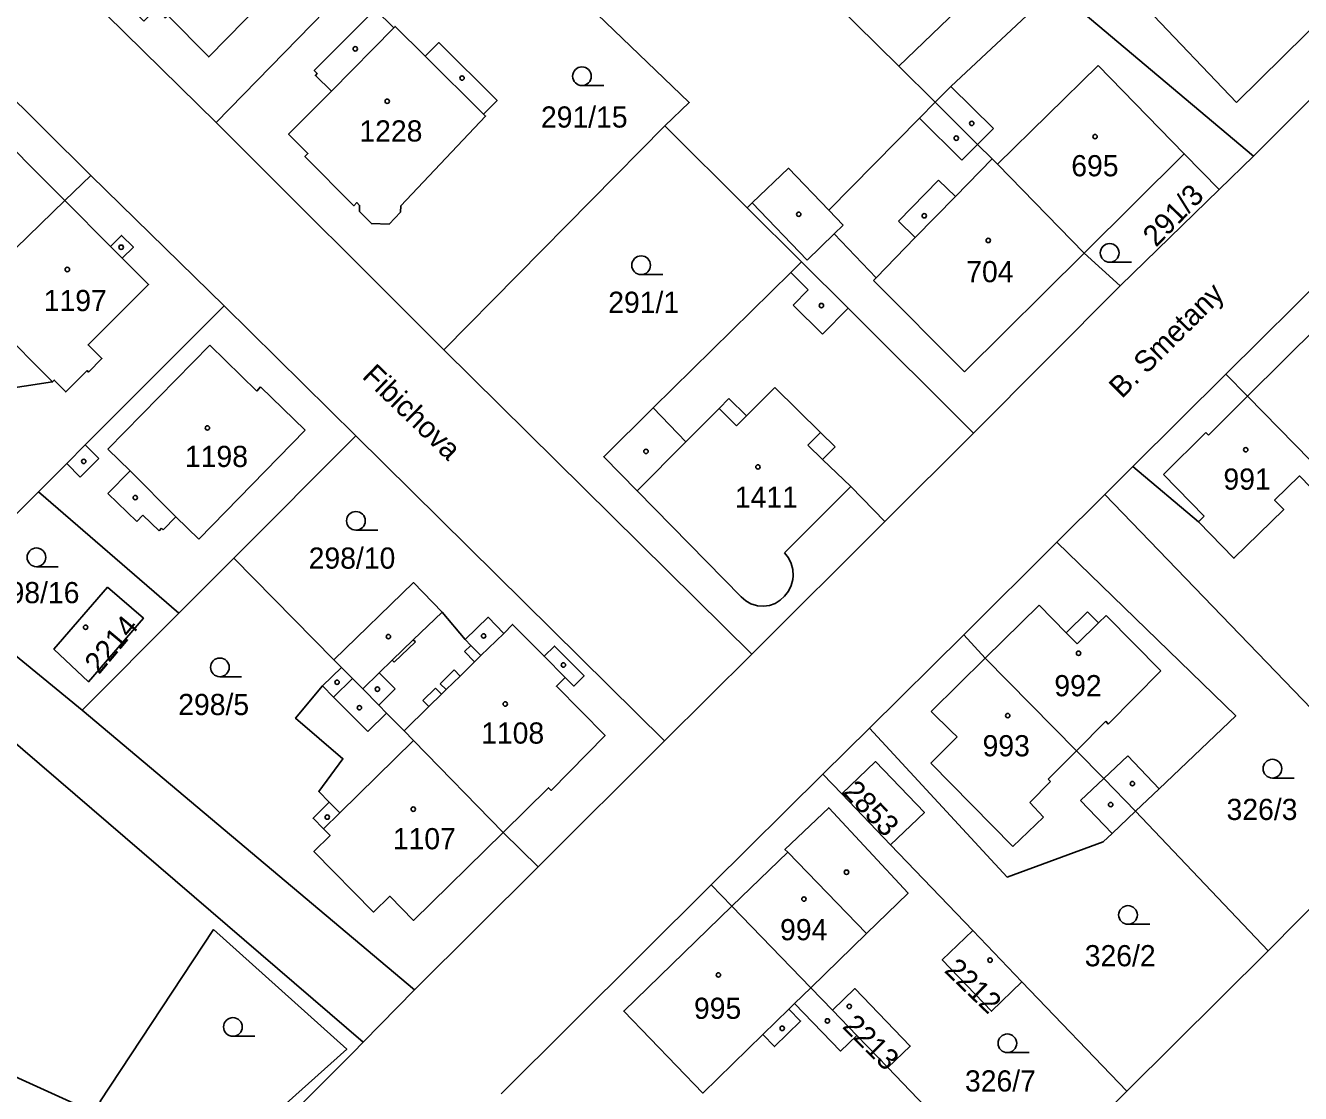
# Model space of a CAD drawing. Extents: x -679220 to -673243, y -1075091 to -1066557.
# Drawn here: x -676221 to -676118.6, y -1072295.1 to -1072209.4 of the extents above; entities that cross this region are included whole.
import ezdxf

# ---------------------------------------------------------------- set-up
doc = ezdxf.new("R2010")
doc.units = 0
for name, color, linetype in [('Hranice parcel', 7, 'Continuous'), ('Parcelní čísla', 7, 'Continuous'), ('Pop  PČ popisy', 7, 'Continuous'), ('Vnitřní kresba', 7, 'Continuous'), ('Značky budov', 7, 'Continuous'), ('Značky kultur', 7, 'Continuous')]:
    doc.layers.add(name, color=color, linetype=linetype)

msp = doc.modelspace()

# ---------------------------------------------------------------- linework, layer by layer
at = {"layer": 'Hranice parcel'}
for p, q in [((-676205.67, -1072217.2), (-676219.22, -1072203.87)), ((-676205.67, -1072217.2), (-676193.21, -1072204.43)), ((-676122.41, -1072219.9), (-676138.34, -1072206.48)), ((-676226.45, -1072210.85), (-676215.72, -1072221.46)), ((-676112.93, -1072210.41), (-676122.41, -1072219.9)), ((-676150.87, -1072212.69), (-676147.97, -1072215.57)), ((-676187.4, -1072235.45), (-676205.67, -1072217.2)), ((-676169.65, -1072217.48), (-676187.4, -1072235.45)), ((-676169.65, -1072217.48), (-676163.05, -1072224.05)), ((-676125.16, -1072222.58), (-676122.41, -1072219.9)), ((-676217.82, -1072223.47), (-676215.72, -1072221.46)), ((-676215.72, -1072221.46), (-676205.02, -1072231.91)), ((-676125.16, -1072222.58), (-676133.11, -1072230.32)), ((-676163.05, -1072224.05), (-676158.7, -1072228.38)), ((-676133.11, -1072230.32), (-676136.01, -1072227.69)), ((-676124.63, -1072237.4), (-676114.69, -1072227.54)), ((-676133.11, -1072230.32), (-676144.89, -1072242.13)), ((-676205.02, -1072231.91), (-676194.46, -1072242.34)), ((-676162.67, -1072259.88), (-676187.4, -1072235.45)), ((-676132.09, -1072244.81), (-676124.63, -1072237.4)), ((-676204.26, -1072252.16), (-676194.46, -1072242.34)), ((-676194.46, -1072242.34), (-676169.68, -1072266.83)), ((-676144.89, -1072242.13), (-676152.01, -1072249.22)), ((-676134.35, -1072247.07), (-676132.09, -1072244.81)), ((-676227.97, -1072254.9), (-676219.92, -1072246.83)), ((-676219.92, -1072246.83), (-676208.66, -1072256.58)), ((-676138.21, -1072250.89), (-676134.35, -1072247.07)), ((-676110, -1072272.34), (-676134.35, -1072247.07)), ((-676152.01, -1072249.22), (-676162.67, -1072259.88)), ((-676145.66, -1072258.33), (-676138.21, -1072250.89)), ((-676208.66, -1072256.58), (-676204.26, -1072252.16)), ((-676196.21, -1072260.33), (-676204.26, -1072252.16)), ((-676216.43, -1072264.37), (-676227.97, -1072254.9)), ((-676208.66, -1072256.58), (-676216.43, -1072264.37)), ((-676153.23, -1072265.81), (-676145.66, -1072258.33)), ((-676169.68, -1072266.83), (-676162.67, -1072259.88)), ((-676196.21, -1072260.33), (-676195.61, -1072260.93)), ((-676189.76, -1072286.8), (-676216.43, -1072264.37)), ((-676156.97, -1072269.5), (-676153.23, -1072265.81)), ((-676169.68, -1072266.83), (-676179.83, -1072276.94)), ((-676156.97, -1072269.5), (-676165.95, -1072278.37)), ((-676155.45, -1072271.09), (-676156.97, -1072269.5)), ((-676151.54, -1072275.17), (-676155.45, -1072271.09)), ((-676121.25, -1072283.67), (-676131.89, -1072272.47)), ((-676110, -1072272.34), (-676121.25, -1072283.67)), ((-676179.83, -1072276.94), (-676182.64, -1072274.17)), ((-676144.94, -1072282.06), (-676151.54, -1072275.17)), ((-676179.83, -1072276.94), (-676189.76, -1072286.8)), ((-676182.79, -1072295.17), (-676165.95, -1072278.37)), ((-676165.95, -1072278.37), (-676164.27, -1072280.1)), ((-676164.27, -1072280.1), (-676157.95, -1072286.65)), ((-676141, -1072286.18), (-676144.94, -1072282.06)), ((-676121.25, -1072283.67), (-676132.59, -1072294.95)), ((-676189.76, -1072286.8), (-676193.86, -1072291)), ((-676157.95, -1072286.65), (-676156.21, -1072288.45)), ((-676132.59, -1072294.95), (-676141, -1072286.18)), ((-676154.26, -1072290.47), (-676156.21, -1072288.45)), ((-676154.26, -1072290.47), (-676151.77, -1072293.05)), ((-676151.77, -1072293.05), (-676141.46, -1072303.74)), ((-676132.59, -1072294.95), (-676141.46, -1072303.74))]:
    msp.add_line(p, q, dxfattribs=at)
for points in [[(-676211.47, -1072209.07), (-676214.42, -1072206.17), (-676213.47, -1072205.21), (-676214.18, -1072204.52), (-676212.05, -1072202.31), (-676213.25, -1072201.15), (-676209.05, -1072196.86), (-676207.81, -1072198.07), (-676206.77, -1072197), (-676199.04, -1072204.56), (-676206.26, -1072211.94), (-676209.56, -1072208.59), (-676209.77, -1072208.81), (-676210.5, -1072208.09), (-676211.47, -1072209.07)], [(-676186.48, -1072197.53), (-676167.7, -1072215.6), (-676169.65, -1072217.48)], [(-676152.53, -1072200.63), (-676157.8, -1072205.82), (-676150.87, -1072212.69)], [(-676152.53, -1072200.63), (-676145.55, -1072207.57), (-676150.87, -1072212.69)], [(-676191.42, -1072209.6), (-676192.91, -1072208.12), (-676197.8, -1072213.04), (-676197.56, -1072213.28), (-676197.7, -1072213.43), (-676196.42, -1072214.7), (-676199.85, -1072218.15), (-676198.3, -1072219.68), (-676198.54, -1072219.92), (-676194.63, -1072223.88), (-676194.38, -1072223.63), (-676194.15, -1072223.86), (-676194.16, -1072224.35), (-676193.21, -1072225.31), (-676191.78, -1072225.35), (-676190.88, -1072224.39), (-676190.84, -1072223.89), (-676184.05, -1072216.69), (-676184.2, -1072216.54), (-676183.12, -1072215.44), (-676187.8, -1072210.79), (-676188.89, -1072211.89), (-676191.31, -1072209.49), (-676191.42, -1072209.6)], [(-676163.05, -1072224.05), (-676162.64, -1072223.66), (-676159.73, -1072220.87), (-676156.51, -1072224.23), (-676149.23, -1072216.85), (-676147.97, -1072215.57)], [(-676147.97, -1072215.57), (-676144.56, -1072218.96), (-676143.39, -1072220.12), (-676142.96, -1072220.54), (-676136.01, -1072227.69)], [(-676217.82, -1072223.47), (-676224.58, -1072216.7), (-676232.42, -1072224.36), (-676231.71, -1072225.07), (-676232.92, -1072226.28), (-676230.15, -1072229.06), (-676231.62, -1072233.42), (-676233.56, -1072235.42), (-676232.97, -1072236), (-676234.24, -1072237.32), (-676232.96, -1072238.57)], [(-676136.01, -1072227.69), (-676127.97, -1072219.71), (-676125.16, -1072222.58)], [(-676233.67, -1072239.3), (-676232.39, -1072240.54), (-676231.14, -1072239.25), (-676230.55, -1072239.82), (-676218.79, -1072238.02), (-676218.66, -1072237.88), (-676217.73, -1072238.82), (-676216.02, -1072237.11), (-676215.91, -1072237.23), (-676214.83, -1072236.15), (-676215.94, -1072235.05), (-676211.09, -1072230.21), (-676213.2, -1072228.1), (-676212.31, -1072227.22), (-676213.27, -1072226.26), (-676214.15, -1072227.15), (-676217.82, -1072223.47)], [(-676232.96, -1072238.57), (-676232.42, -1072238.01), (-676231.68, -1072237.25), (-676229.74, -1072235.25), (-676227.74, -1072233.19), (-676225.7, -1072231.1), (-676217.82, -1072223.47)], [(-676158.7, -1072228.38), (-676159.56, -1072229.25), (-676170.59, -1072240.11), (-676174.56, -1072244.03), (-676171.89, -1072246.75), (-676163.53, -1072255.26)], [(-676158.7, -1072228.38), (-676154.95, -1072232.11), (-676144.89, -1072242.13)], [(-676205.02, -1072231.91), (-676216.17, -1072243.08), (-676217.66, -1072244.57), (-676219.92, -1072246.83)], [(-676193.86, -1072291), (-676233.43, -1072257.02), (-676238.04, -1072259.58), (-676249.06, -1072250.49), (-676247.36, -1072245.21), (-676260.59, -1072233.8)], [(-676124.63, -1072237.4), (-676122.89, -1072239.16), (-676114.06, -1072248.19)], [(-676132.09, -1072244.81), (-676126.84, -1072249.24), (-676123.99, -1072252.17), (-676119.99, -1072248.27), (-676120.73, -1072247.51), (-676118.73, -1072245.57), (-676115.14, -1072249.25), (-676114.06, -1072248.19)], [(-676160.05, -1072251.74), (-676154.74, -1072246.42), (-676152.01, -1072249.22)], [(-676131.89, -1072272.47), (-676130, -1072270.68), (-676123.84, -1072264.82), (-676138.21, -1072250.89)], [(-676163.53, -1072255.26), (-676163.17, -1072255.58), (-676162.76, -1072255.82), (-676162.3, -1072255.97), (-676162.22, -1072255.99), (-676161.74, -1072256.03), (-676161.27, -1072255.96), (-676160.81, -1072255.8), (-676160.4, -1072255.55), (-676160.05, -1072255.22), (-676159.74, -1072254.82), (-676159.52, -1072254.36), (-676159.4, -1072253.88), (-676159.37, -1072253.59), (-676159.4, -1072253.08), (-676159.52, -1072252.6), (-676159.74, -1072252.14), (-676160.05, -1072251.74)], [(-676214.39, -1072254.49), (-676218.69, -1072259.46), (-676215.91, -1072262.09), (-676211.5, -1072256.99), (-676214.39, -1072254.49)], [(-676182.64, -1072274.17), (-676179, -1072270.59), (-676178.79, -1072270.81), (-676174.46, -1072266.4), (-676178.36, -1072262.44), (-676177.66, -1072261.74), (-676176.97, -1072262.43), (-676176.14, -1072261.61), (-676178.52, -1072259.22), (-676179.35, -1072260.04), (-676181.88, -1072257.49), (-676182.59, -1072258.2), (-676183.85, -1072256.91), (-676185.68, -1072258.7), (-676187.53, -1072256.49), (-676189.84, -1072254.13), (-676196.21, -1072260.33)], [(-676145.66, -1072258.33), (-676143.94, -1072260.19), (-676136.63, -1072267.63), (-676134.44, -1072269.86), (-676131.89, -1072272.47)], [(-676195.61, -1072260.93), (-676197.12, -1072262.42), (-676199.29, -1072265.02), (-676195.49, -1072268.27), (-676197.43, -1072270.89), (-676196.59, -1072271.75), (-676197.89, -1072273.04), (-676197.05, -1072273.9), (-676196.52, -1072274.43), (-676197.82, -1072275.71), (-676193.03, -1072280.57), (-676191.74, -1072279.3), (-676189.84, -1072281.24), (-676182.64, -1072274.17)], [(-676182.64, -1072274.17), (-676189.83, -1072266.79), (-676190.59, -1072266.02), (-676191.99, -1072264.6), (-676192.62, -1072263.96), (-676193.9, -1072262.66), (-676194.73, -1072261.82), (-676195.61, -1072260.93)], [(-676277.39, -1072266.08), (-676260.33, -1072276.26), (-676204.45, -1072301.67)], [(-676153.23, -1072265.81), (-676142.19, -1072277.76), (-676134.47, -1072274.92), (-676133.77, -1072274.26), (-676131.89, -1072272.47)], [(-676155.45, -1072271.09), (-676152.74, -1072268.49), (-676148.83, -1072272.58), (-676151.54, -1072275.17)], [(-676157.95, -1072286.65), (-676153.48, -1072282.29), (-676150.14, -1072279.04), (-676156.5, -1072272.2), (-676160.02, -1072275.55), (-676159.8, -1072275.77), (-676164.27, -1072280.1)], [(-676164.27, -1072280.1), (-676172.96, -1072288.52), (-676166.6, -1072295.09), (-676161.8, -1072290.4), (-676160.86, -1072291.37), (-676158.76, -1072289.32), (-676159.7, -1072288.36), (-676159.26, -1072287.91), (-676155.57, -1072291.73), (-676154.26, -1072290.47)], [(-676214.99, -1072295.79), (-676205.87, -1072281.98), (-676195.19, -1072291.56), (-676204.92, -1072300.28), (-676214.99, -1072295.79)], [(-676141, -1072286.18), (-676143.45, -1072288.53), (-676147.39, -1072284.41), (-676144.94, -1072282.06)], [(-676156.21, -1072288.45), (-676154.42, -1072286.71), (-676149.97, -1072291.32), (-676151.77, -1072293.05)], [(-676204.45, -1072301.67), (-676194.68, -1072291.84), (-676193.86, -1072291)]]:
    msp.add_lwpolyline(points, dxfattribs=at)
at = {"layer": 'Vnitřní kresba'}
for p, q in [((-676146.7, -1072214.3), (-676138.34, -1072206.48)), ((-676123.79, -1072215.59), (-676115.76, -1072207.69)), ((-676130.98, -1072208.06), (-676123.79, -1072215.59)), ((-676191.42, -1072209.6), (-676196.42, -1072214.7)), ((-676188.89, -1072211.89), (-676184.2, -1072216.54)), ((-676134.88, -1072212.64), (-676142.96, -1072220.54)), ((-676127.97, -1072219.71), (-676134.88, -1072212.64)), ((-676147.97, -1072215.57), (-676146.7, -1072214.3)), ((-676146.7, -1072214.3), (-676143.29, -1072217.68)), ((-676145.83, -1072220.23), (-676149.23, -1072216.85)), ((-676143.29, -1072217.68), (-676144.56, -1072218.96)), ((-676144.56, -1072218.96), (-676145.83, -1072220.23)), ((-676143.39, -1072220.12), (-676146.34, -1072223.15)), ((-676147.7, -1072221.82), (-676150.92, -1072225.11)), ((-676146.34, -1072223.15), (-676147.7, -1072221.82)), ((-676149.56, -1072226.44), (-676146.34, -1072223.15)), ((-676158.25, -1072228.24), (-676162.64, -1072223.66)), ((-676155.34, -1072225.45), (-676156.51, -1072224.23)), ((-676150.92, -1072225.11), (-676149.56, -1072226.44)), ((-676156.07, -1072226.15), (-676158.25, -1072228.24)), ((-676156.07, -1072226.15), (-676155.34, -1072225.45)), ((-676152.7, -1072229.66), (-676156.07, -1072226.15)), ((-676149.56, -1072226.44), (-676152.7, -1072229.66)), ((-676214.15, -1072227.15), (-676213.2, -1072228.1)), ((-676136.01, -1072227.69), (-676145.62, -1072237.22)), ((-676159.56, -1072229.25), (-676158.16, -1072230.64)), ((-676152.91, -1072229.87), (-676152.7, -1072229.66)), ((-676145.62, -1072237.22), (-676152.91, -1072229.87)), ((-676225.7, -1072231.1), (-676218.79, -1072238.02)), ((-676158.16, -1072230.64), (-676159.36, -1072231.85)), ((-676159.36, -1072231.85), (-676157.01, -1072234.18)), ((-676157.01, -1072234.18), (-676154.95, -1072232.11)), ((-676122.89, -1072239.16), (-676117.16, -1072233.48)), ((-676214.35, -1072243.42), (-676206.18, -1072235.06)), ((-676206.18, -1072235.06), (-676202.39, -1072238.76)), ((-676202.39, -1072238.76), (-676202.1, -1072238.41)), ((-676202.1, -1072238.41), (-676198.51, -1072241.9)), ((-676163.1, -1072240.75), (-676160.82, -1072238.46)), ((-676160.82, -1072238.46), (-676157.17, -1072242.07)), ((-676165.31, -1072240.15), (-676164.51, -1072239.34)), ((-676164.51, -1072239.34), (-676163.1, -1072240.75)), ((-676126.04, -1072242.29), (-676122.89, -1072239.16)), ((-676170.59, -1072240.11), (-676167.97, -1072242.82)), ((-676167.97, -1072242.82), (-676165.31, -1072240.15)), ((-676165.31, -1072240.15), (-676163.9, -1072241.55)), ((-676163.9, -1072241.55), (-676163.1, -1072240.75)), ((-676198.51, -1072241.9), (-676207.05, -1072250.64)), ((-676157.17, -1072242.07), (-676158.17, -1072243.09)), ((-676157.17, -1072242.07), (-676156, -1072243.23)), ((-676129.65, -1072245.45), (-676126.25, -1072242.08)), ((-676126.25, -1072242.08), (-676126.04, -1072242.29)), ((-676215.08, -1072244.17), (-676216.17, -1072243.08)), ((-676212.57, -1072245.16), (-676214.35, -1072243.42)), ((-676171.89, -1072246.75), (-676167.97, -1072242.82)), ((-676158.17, -1072243.09), (-676157, -1072244.24)), ((-676156, -1072243.23), (-676157, -1072244.24)), ((-676217.66, -1072244.57), (-676216.57, -1072245.66)), ((-676216.57, -1072245.66), (-676215.08, -1072244.17)), ((-676157, -1072244.24), (-676154.74, -1072246.42)), ((-676214.35, -1072246.98), (-676212.57, -1072245.16)), ((-676212.57, -1072245.16), (-676208.9, -1072248.84)), ((-676126.39, -1072248.8), (-676129.65, -1072245.45)), ((-676212.04, -1072249.23), (-676214.35, -1072246.98)), ((-676211.54, -1072248.71), (-676212.04, -1072249.23)), ((-676210.24, -1072249.97), (-676211.54, -1072248.71)), ((-676208.9, -1072248.84), (-676209.91, -1072249.88)), ((-676207.05, -1072250.64), (-676208.9, -1072248.84)), ((-676126.84, -1072249.24), (-676126.39, -1072248.8)), ((-676210.04, -1072249.76), (-676210.24, -1072249.97)), ((-676209.91, -1072249.88), (-676210.04, -1072249.76)), ((-676143.94, -1072260.19), (-676139.63, -1072255.94)), ((-676139.63, -1072255.94), (-676137.45, -1072258.16)), ((-676189.85, -1072258.71), (-676187.53, -1072256.49)), ((-676137.45, -1072258.16), (-676135.74, -1072256.47)), ((-676135.74, -1072256.47), (-676134.86, -1072257.36)), ((-676134.86, -1072257.36), (-676134.25, -1072256.76)), ((-676134.25, -1072256.76), (-676129.85, -1072261.22)), ((-676136.57, -1072259.05), (-676137.45, -1072258.16)), ((-676134.86, -1072257.36), (-676136.57, -1072259.05)), ((-676189.85, -1072258.71), (-676191.55, -1072260.34)), ((-676191.38, -1072260.52), (-676189.68, -1072258.89)), ((-676189.68, -1072258.89), (-676189.85, -1072258.71)), ((-676185.22, -1072259.17), (-676185.74, -1072259.67)), ((-676185.22, -1072259.17), (-676185.68, -1072258.7)), ((-676184.42, -1072259.99), (-676185.22, -1072259.17)), ((-676182.59, -1072258.2), (-676184.42, -1072259.99)), ((-676185.74, -1072259.67), (-676184.93, -1072260.49)), ((-676184.93, -1072260.49), (-676184.42, -1072259.99)), ((-676177.66, -1072261.74), (-676179.35, -1072260.04)), ((-676148.28, -1072264.47), (-676143.94, -1072260.19)), ((-676192.59, -1072261.36), (-676191.55, -1072260.34)), ((-676191.55, -1072260.34), (-676191.38, -1072260.52)), ((-676186.57, -1072261.14), (-676187.69, -1072262.24)), ((-676186.09, -1072261.63), (-676186.57, -1072261.14)), ((-676184.93, -1072260.49), (-676186.09, -1072261.63)), ((-676129.85, -1072261.22), (-676134.07, -1072265.48)), ((-676196.24, -1072263.31), (-676194.73, -1072261.82)), ((-676192.59, -1072261.36), (-676193.9, -1072262.66)), ((-676191.31, -1072262.66), (-676192.59, -1072261.36)), ((-676187.69, -1072262.24), (-676187.22, -1072262.72)), ((-676187.22, -1072262.72), (-676186.09, -1072261.63)), ((-676196.24, -1072263.31), (-676197.12, -1072262.42)), ((-676192.62, -1072263.96), (-676191.31, -1072262.66)), ((-676188.06, -1072262.6), (-676189.08, -1072263.6)), ((-676188.61, -1072264.08), (-676187.59, -1072263.09)), ((-676187.59, -1072263.09), (-676188.06, -1072262.6)), ((-676187.22, -1072262.72), (-676187.59, -1072263.09)), ((-676193.5, -1072266.09), (-676196.24, -1072263.31)), ((-676188.61, -1072264.08), (-676190.59, -1072266.02)), ((-676189.08, -1072263.6), (-676188.61, -1072264.08)), ((-676191.99, -1072264.6), (-676193.5, -1072266.09)), ((-676148.28, -1072264.47), (-676146.68, -1072266.06)), ((-676136.63, -1072267.63), (-676134.28, -1072265.26)), ((-676134.28, -1072265.26), (-676134.07, -1072265.48)), ((-676146.68, -1072266.06), (-676146.19, -1072266.51)), ((-676195.75, -1072272.61), (-676189.83, -1072266.79)), ((-676146.19, -1072266.51), (-676148.3, -1072268.63)), ((-676138.89, -1072269.91), (-676136.63, -1072267.63)), ((-676134.44, -1072269.86), (-676132.51, -1072268.03)), ((-676132.51, -1072268.03), (-676130, -1072270.68)), ((-676148.3, -1072268.63), (-676141.73, -1072275.32)), ((-676140.38, -1072271.78), (-676138.7, -1072270.1)), ((-676138.7, -1072270.1), (-676138.89, -1072269.91)), ((-676136.29, -1072271.61), (-676134.44, -1072269.86)), ((-676195.75, -1072272.61), (-676196.59, -1072271.75)), ((-676139.26, -1072272.94), (-676140.38, -1072271.78)), ((-676133.77, -1072274.26), (-676136.29, -1072271.61)), ((-676197.05, -1072273.9), (-676195.75, -1072272.61)), ((-676141.73, -1072275.32), (-676139.26, -1072272.94)), ((-676153.48, -1072282.29), (-676159.8, -1072275.77)), ((-676159.26, -1072287.91), (-676157.95, -1072286.65)), ((-676161.8, -1072290.4), (-676159.7, -1072288.36))]:
    msp.add_line(p, q, dxfattribs=at)
at = {"layer": 'Značky budov'}
for centre in [(-676194.5, -1072211.29), (-676185.93, -1072213.64), (-676191.94, -1072215.5), (-676145.03, -1072217.27), (-676135.13, -1072218.33), (-676146.27, -1072218.46), (-676158.91, -1072224.57), (-676148.84, -1072224.69), (-676213.29, -1072227.21), (-676143.7, -1072226.67), (-676217.61, -1072229), (-676157.09, -1072231.89), (-676206.37, -1072241.71), (-676171.17, -1072243.6), (-676123.04, -1072243.46), (-676216.29, -1072244.4), (-676162.19, -1072244.84), (-676212.16, -1072247.31), (-676216.14, -1072257.71), (-676191.84, -1072258.46), (-676184.2, -1072258.41), (-676136.46, -1072259.8), (-676177.8, -1072260.74), (-676195.96, -1072262.13), (-676192.73, -1072262.68), (-676194.17, -1072264.17), (-676182.46, -1072263.87), (-676142.14, -1072264.8), (-676132.14, -1072270.26), (-676189.85, -1072272.31), (-676133.88, -1072271.94), (-676196.75, -1072272.95), (-676155.08, -1072277.37), (-676158.5, -1072279.53), (-676143.56, -1072284.43), (-676165.36, -1072285.61), (-676154.86, -1072288.14), (-676160.24, -1072289.9), (-676156.61, -1072289.3)]:
    msp.add_circle(centre, 0.175, dxfattribs=at)
at = {"layer": 'Značky kultur'}
for p, q in [((-676176.31, -1072214.24), (-676174.56, -1072214.24)), ((-676133.96, -1072228.42), (-676132.21, -1072228.42)), ((-676171.56, -1072229.41), (-676169.81, -1072229.41)), ((-676194.45, -1072249.92), (-676192.7, -1072249.92)), ((-676220.09, -1072252.85), (-676218.34, -1072252.85)), ((-676205.37, -1072261.68), (-676203.62, -1072261.68)), ((-676120.9, -1072269.81), (-676119.15, -1072269.81)), ((-676132.49, -1072281.55), (-676130.74, -1072281.55)), ((-676204.32, -1072290.54), (-676202.57, -1072290.54)), ((-676142.17, -1072291.85), (-676140.42, -1072291.85))]:
    msp.add_line(p, q, dxfattribs=at)
for centre in [(-676176.31, -1072213.49), (-676133.96, -1072227.67), (-676171.56, -1072228.66), (-676194.45, -1072249.17), (-676220.09, -1072252.1), (-676205.37, -1072260.93), (-676120.9, -1072269.06), (-676132.49, -1072280.8), (-676204.32, -1072289.79), (-676142.17, -1072291.1)]:
    msp.add_circle(centre, 0.75, dxfattribs=at)

# ---------------------------------------------------------------- texts
at = {"layer": 'Parcelní čísla'}
for s, p in [('291/15', (-676179.6, -1072217.61)), ('1228', (-676194.17, -1072218.73)), ('695', (-676137.04, -1072221.52)), ('704', (-676145.47, -1072230.02)), ('1197', (-676219.5, -1072232.34)), ('291/1', (-676174.2, -1072232.48)), ('1198', (-676208.17, -1072244.85)), ('991', (-676124.83, -1072246.67)), ('1411', (-676164.04, -1072248.12)), ('298/10', (-676198.24, -1072253.01)), ('298/16', (-676223.59, -1072255.78)), ('992', (-676138.4, -1072263.25)), ('298/5', (-676208.71, -1072264.76)), ('1108', (-676184.4, -1072267.05)), ('993', (-676144.16, -1072268.07)), ('326/3', (-676124.58, -1072273.18)), ('1107', (-676191.49, -1072275.53)), ('994', (-676160.41, -1072282.83)), ('326/2', (-676135.96, -1072284.92)), ('995', (-676167.32, -1072289.14)), ('326/7', (-676145.57, -1072294.97))]:
    msp.add_text(s, height=1.7, dxfattribs=at).set_placement(p)
for s, rotation, p in [('291/3', 46, (-676130.24, -1072227.27)), ('2214', 50, (-676215.07, -1072261.56)), ('2853', 314, (-676155.46, -1072271)), ('2212', 316, (-676147.31, -1072285.33)), ('2213', 315, (-676155.49, -1072289.82))]:
    msp.add_text(s, height=1.7, rotation=rotation, dxfattribs=at).set_placement(p)
at = {"layer": 'Pop  PČ popisy'}
for s, rotation, p in [('B. Smetany', 45, (-676132.98, -1072239.41)), ('Fibichova', 316, (-676194.04, -1072237.66))]:
    msp.add_text(s, height=1.7, rotation=rotation, dxfattribs=at).set_placement(p)

doc.saveas('drawing.dxf')
